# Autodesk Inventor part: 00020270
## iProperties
Created: 2011-05
Part Number: 00020270
Document SubType Name: Modeling
Designer: Administrator
Density: 2.71 g/cm^3
Material: Aluminum-6061
Mass: 208.107 g
Surface Area: 282.939 cm^2
Volume: 76.7922 cm^3
Author: Administrator
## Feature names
1. Base1
